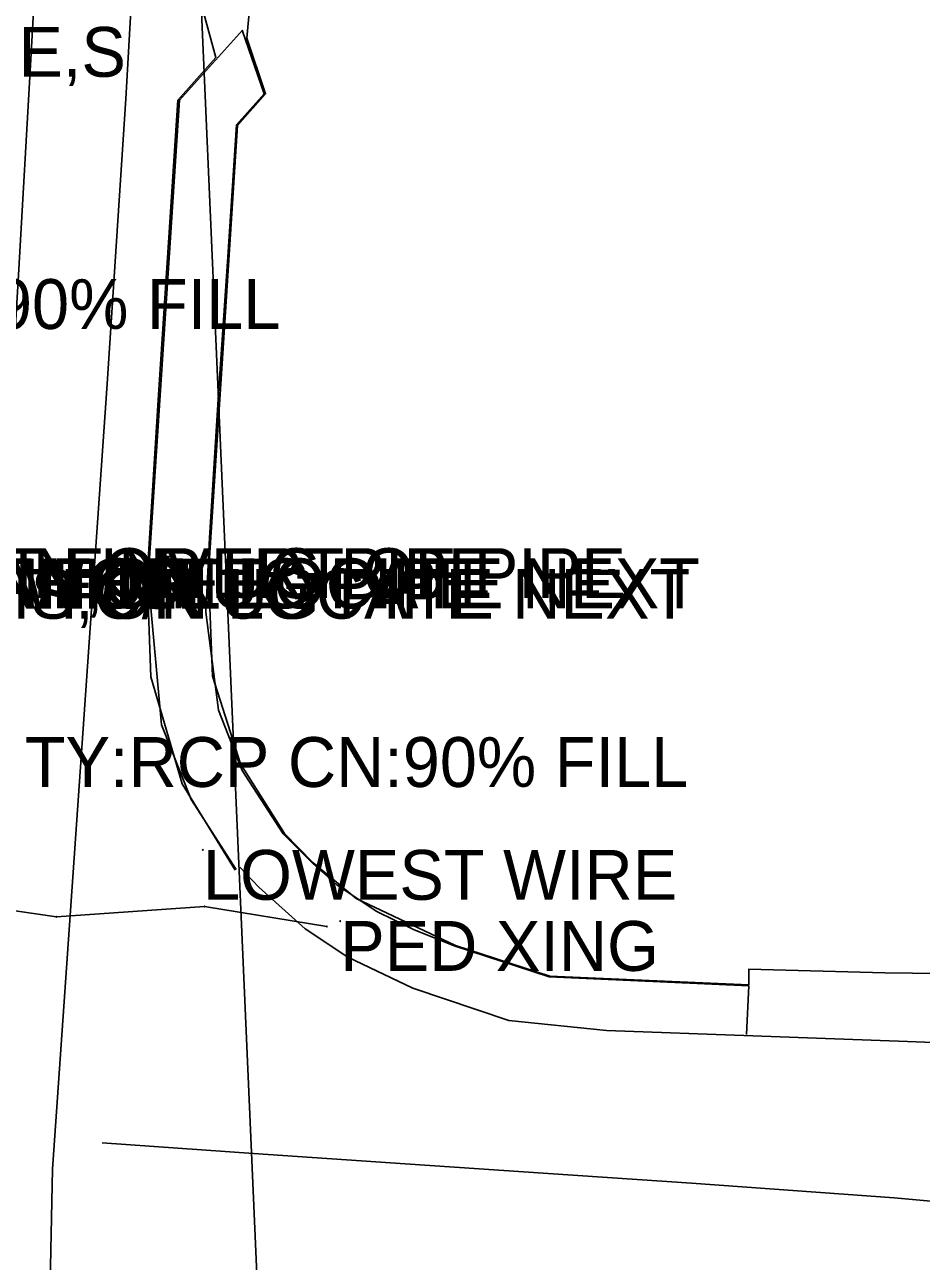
# Model space of a CAD drawing. Extents: x 997398 to 1003416, y 334596 to 337085.
# Drawn here: x 999247.8 to 999337.6, y 335281.4 to 335405.4 of the extents above; entities that cross this region are included whole.
import ezdxf

# ---------------------------------------------------------------- set-up
doc = ezdxf.new("R2010")
doc.units = 0
for name, color, linetype in [('Default', 7, 'Continuous'), ('S_CURB', 7, 'Continuous'), ('S_EDGE_PAVEMENT', 7, 'Continuous'), ('S_ELECTRIC_UTILITIES_ANNOT', 7, 'Continuous'), ('S_GAS_UTILITIES', 7, 'Continuous'), ('S_GRD_PT_SYM', 7, 'Continuous'), ('S_MANHOLE_ANNOT', 7, 'Continuous'), ('S_MISC_TOPO_POINT', 7, 'Continuous'), ('S_MSC_PT_SYM', 7, 'Continuous'), ('S_PAVEMENT_CROWN', 7, 'Continuous'), ('S_SANITARY_SEWER_ANNOT', 7, 'Continuous'), ('S_SIDE_DRAIN_ANNOT', 7, 'Continuous'), ('S_SIDEWALK', 7, 'Continuous'), ('S_SURVEY_TEXT_ANNOT', 7, 'Continuous'), ('S_UTILITY_POLE_ANNOT', 7, 'Continuous'), ('S_UTL_PT_SYM', 7, 'Continuous')]:
    doc.layers.add(name, color=color, linetype=linetype)

msp = doc.modelspace()

# ---------------------------------------------------------------- linework, layer by layer
at = {"layer": 'Default'}
msp.add_line((999272.07, 335256.17), (999254.77, 335651.12), dxfattribs=at)
at = {"layer": 'S_CURB'}
msp.add_lwpolyline([(999403.71, 335300.85), (999389.91, 335301.36), (999376.11, 335301.88), (999356.19, 335302.64), (999336.26, 335303.4), (999320.74, 335304), (999306.07, 335304.52), (999296.29, 335305.51), (999286.68, 335308.77), (999280.16, 335311.86), (999275.88, 335314.72), (999271.24, 335318.89), (999269.34, 335320.89)], dxfattribs=at)
at = {"layer": 'S_EDGE_PAVEMENT'}
for points in [[(999250.53, 335290.61), (999251.9, 335310.31), (999253.28, 335330), (999254.66, 335349.69), (999256.03, 335369.39), (999256.96, 335383.69), (999257.89, 335397.99), (999259.31, 335422.72), (999260.17, 335436.32), (999261.04, 335449.92), (999261.9, 335463.52), (999262.77, 335477.12), (999265.06, 335501.55), (999266.67, 335519.12), (999268.27, 335536.68), (999270.61, 335550.38), (999272.95, 335564.07), (999275.29, 335577.76), (999277.63, 335591.45)], [(999268.87, 335320.6), (999263.53, 335329.26), (999260.4, 335340), (999260.03, 335350.15), (999261.25, 335369.32), (999262.19, 335383.58), (999263.12, 335397.84), (999266.91, 335402.13), (999261.38, 335422.51), (999262.14, 335435.92), (999262.89, 335449.33), (999263.64, 335462.75), (999264.4, 335476.16), (999272.66, 335481.44), (999281.46, 335481.65), (999283.33, 335495.44), (999285.2, 335509.23), (999269.56, 335528.03), (999269.81, 335536.47), (999271.83, 335550.21), (999273.84, 335563.95), (999275.86, 335577.69), (999277.88, 335591.43)], [(999345.08, 335310.18), (999333.98, 335310.31), (999320.35, 335310.66), (999320.34, 335309.11), (999300.42, 335309.96), (999290.95, 335313.05), (999280.99, 335317.76), (999276.64, 335321.37), (999273.81, 335324.29), (999269.4, 335331.28), (999266.59, 335340.08), (999266.2, 335350.38), (999267.62, 335372.46), (999269.1, 335395.3), (999271.9, 335398.47), (999270.02, 335404.05), (999271.44, 335419.38), (999272.86, 335434.71), (999274.05, 335454.26), (999275.25, 335473.81), (999289.66, 335472.83), (999288.8, 335477.03), (999282.16, 335481.48), (999283.77, 335495.62)], [(999250.53, 335290.61), (999250.16, 335271.12), (999249.78, 335251.63)]]:
    msp.add_lwpolyline(points, dxfattribs=at)
at = {"layer": 'S_GAS_UTILITIES'}
for p, q in [((999224.19, 335319.8), (999250.94, 335315.93)), ((999250.94, 335315.93), (999265.79, 335316.97)), ((999265.79, 335316.97), (999278.05, 335314.94))]:
    msp.add_line(p, q, dxfattribs=at)
at = {"layer": 'S_GRD_PT_SYM'}
msp.add_lwpolyline([(999265.63, 335322.63), (999265.63, 335322.68), (999265.63, 335322.63), (999265.58, 335322.63), (999265.63, 335322.63), (999265.63, 335322.58), (999265.63, 335322.63), (999265.68, 335322.63)], dxfattribs=at)
at = {"layer": 'S_MSC_PT_SYM'}
msp.add_lwpolyline([(999279.39, 335315.5), (999279.39, 335315.55), (999279.39, 335315.5), (999279.34, 335315.5), (999279.39, 335315.5), (999279.39, 335315.45), (999279.39, 335315.5), (999279.44, 335315.5)], dxfattribs=at)
at = {"layer": 'S_PAVEMENT_CROWN'}
for points in [[(999240.93, 335269.15), (999242.42, 335292.45), (999243.36, 335312.31), (999244.3, 335332.17), (999245.73, 335356.52), (999247.17, 335380.88), (999248.33, 335401.35), (999249.49, 335421.83), (999250.52, 335439.55), (999251.54, 335457.27), (999252.57, 335474.99), (999253.6, 335492.71), (999255.46, 335505.53), (999257.33, 335518.35), (999259.19, 335531.16), (999261.06, 335543.98), (999262.92, 335556.8), (999264.79, 335569.61), (999266.65, 335582.43), (999268.52, 335595.25), (999272.87, 335613.5), (999277.22, 335631.74), (999281.77, 335646.2)], [(999481.36, 335281.6), (999467.73, 335281.58), (999454.1, 335281.56), (999440.47, 335281.53), (999426.85, 335281.51), (999403.67, 335282.53), (999380.49, 335283.56), (999357.71, 335285.65), (999334.94, 335287.74), (999314.61, 335289.19), (999300.25, 335290.16), (999285.89, 335291.13), (999270.7, 335292.19), (999255.51, 335293.25)]]:
    msp.add_lwpolyline(points, dxfattribs=at)
at = {"layer": 'S_SIDEWALK'}
for points in [[(999268.95, 335320.67), (999264.46, 335327.68), (999261.48, 335335.18), (999260.14, 335349.87), (999261.71, 335373.86), (999263.28, 335397.86), (999269.59, 335404.87)], [(999320.12, 335304.11), (999320.34, 335309), (999300.35, 335309.91), (999290.9, 335312.97), (999286.81, 335314.61), (999283.01, 335316.48), (999279.05, 335319.14), (999276.6, 335321.3), (999273.66, 335324.24), (999269.57, 335330.59), (999267.19, 335336.65), (999265.91, 335346.49), (999266.28, 335353.94), (999267.22, 335368.92), (999268.11, 335382.14), (999268.99, 335395.36), (999271.76, 335398.49), (999269.57, 335404.88)]]:
    msp.add_lwpolyline(points, dxfattribs=at)
at = {"layer": 'S_UTL_PT_SYM'}
for points in [[(999265.63, 335322.63), (999265.63, 335322.68), (999265.63, 335322.63), (999265.58, 335322.63), (999265.63, 335322.63), (999265.63, 335322.58), (999265.63, 335322.63), (999265.68, 335322.63)], [(999265.79, 335316.97), (999265.79, 335317.02), (999265.79, 335316.97), (999265.74, 335316.97), (999265.79, 335316.97), (999265.79, 335316.92), (999265.79, 335316.97), (999265.84, 335316.97)], [(999250.94, 335315.93), (999250.94, 335315.98), (999250.94, 335315.93), (999250.89, 335315.93), (999250.94, 335315.93), (999250.94, 335315.88), (999250.94, 335315.93), (999250.99, 335315.93)], [(999278.05, 335314.94), (999278.05, 335314.99), (999278.05, 335314.94), (999278, 335314.94), (999278.05, 335314.94), (999278.05, 335314.89), (999278.05, 335314.94), (999278.1, 335314.94)]]:
    msp.add_lwpolyline(points, dxfattribs=at)

# ---------------------------------------------------------------- texts
at = {"layer": 'S_ELECTRIC_UTILITIES_ANNOT'}
msp.add_text('LOWEST WIRE', height=5, dxfattribs=at).set_placement((999265.63, 335317.63))
at = {"layer": 'S_MANHOLE_ANNOT'}
msp.add_text('BOTTOM OF MANHOLE', height=5, dxfattribs=at).set_placement((999197.21, 335346.84))
at = {"layer": 'S_MISC_TOPO_POINT'}
for p in [(999197.31, 335347.9), (999196.21, 335346.87), (999197.08, 335345.83)]:
    msp.add_text('SURFACE SHOT FOR UG PIPE', height=5, dxfattribs=at).set_placement(p)
at = {"layer": 'S_SANITARY_SEWER_ANNOT'}
for s, p in [('DI:6 TY:PVC TO N INVERT OF PIPE', (999197.31, 335347.9)), ('DI:6 TY:PVC TO W,C/N LOCATE NEXT', (999196.21, 335346.87)), ('TOP CL OF MANHOLE', (999197.21, 335346.84)), ('DI:6 TY:PVC TO S,C/N LOCATE NEXT', (999197.08, 335345.83))]:
    msp.add_text(s, height=5, dxfattribs=at).set_placement(p)
at = {"layer": 'S_SIDE_DRAIN_ANNOT'}
for s, p in [('CN:90% FILL', (999233.26, 335374.89)), ('DI:10 TY:RCP CN:90% FILL', (999229.93, 335328.95))]:
    msp.add_text(s, height=5, dxfattribs=at).set_placement(p)
at = {"layer": 'S_SURVEY_TEXT_ANNOT'}
msp.add_text('PED XING', height=5, dxfattribs=at).set_placement((999279.39, 335310.5))
at = {"layer": 'S_UTILITY_POLE_ANNOT'}
msp.add_text('OHE NE,S', height=5, dxfattribs=at).set_placement((999225.95, 335400.19))

doc.saveas('drawing.dxf')
